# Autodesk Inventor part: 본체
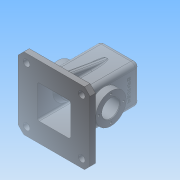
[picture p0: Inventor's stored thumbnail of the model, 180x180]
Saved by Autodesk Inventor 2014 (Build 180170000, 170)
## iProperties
Created: 2016-02
Part Number: 본체
Material: 일반
Document SubType Name: Modeling
Designer: net
Density: 1 g/cm^3
Appearance: 기본값
Author: net
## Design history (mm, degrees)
sketch "스케치1"
  geometry: L1 (55, -65)-(-55, -65); L2 (-65, -55)-(-65, 55); L3 (-55, 65)-(55, 65); L4 (65, 55)-(65, -55); L5 (55, -65)-(65, -55); L6 (65, 55)-(55, 65); L7 (-55, 65)-(-65, 55); L8 (-65, -55)-(-55, -65); 5 further points
  constraints: 16 end point, 8 point on line, 2 parallel, 1 horizontal, 1 perpendicular
  dimensions: "d0" = 130 distance of point (65, -65) point (-65, -65); "d1" = 130 distance of point (-65, -65) point (-65, 65); "d2" = 65 distance from line of point (0, 0) L4; "d3" = 65 distance from line of point (0, 0) L1; "d4" = 10 distance of L1.start point (65, -65); "d5" = 10 distance of L4.end point (65, -65) (= d4); "d6" = 10 distance of L4.start point (65, 65) (= d4); "d7" = 10 distance of L3.end point (65, 65) (= d6); "d8" = 10 distance of L3.start point (-65, 65) (= d4); "d9" = 10 distance of L2.end point (-65, 65) (= d8); "d10" = 10 distance of L2.start point (-65, -65) (= d4); "d11" = 10 distance of L1.end point (-65, -65) (= d10)
extrude "돌출1" new body sketch "스케치1" distance "d12" = 10; taper "d13" = 0 deg
sketch "스케치2"
  geometry: L1 (-35, 35)-(35, 35); L2 (35, 35)-(35, -35); L3 (35, -35)-(-35, -35); L4 (-35, -35)-(-35, 35); 1 further point
  constraints: 8 end point, 2 parallel, 1 horizontal, 1 perpendicular
  dimensions: "d14" = 70 distance of L1.start L1.end; "d15" = 70 distance of L1.end L2.end; "d16" = 35 distance from line of point (0, 0) L1; "d17" = 35 distance from line of point (0, 0) L2
extrude "돌출2" join sketch "스케치2" distance "d18" = 110; taper "d19" = 0 deg
sketch "스케치3"
  geometry: L1 (0, 65)-(10, 65) reference; L2 (10, 65)-(10, 50); L3 (10, 50)-(95.069, 35); L4 (10, 35)-(120, 35) reference; L5 (10, 50)-(10, 35); L6 (10, 35)-(95.069, 35); L7 (10, -50)-(95.069, -35); L8 (10, -50)-(10, -35); L9 (10, -35)-(95.069, -35); L10 (120, -35)-(120, 35) reference; L11 (10, -35)-(120, -35) reference; L12 (-12.76, 30)-(115, 30); L13 (115, 30)-(115, -30); L14 (115, -30)-(-12.76, -30); L15 (-12.76, 30)-(-12.76, -30); 1 further point
  constraints: 22 end point, 3 perpendicular
  dimensions: "d20" = 15 distance of L1.end L2.end; "d21" = 10 deg angle of L1 L3; "d22" = 5 distance between parallel lines of L12 L4; "d23" = 5 distance between parallel lines of L10 L13; "d24" = 5 distance between parallel lines of L11 L14
extrude "돌출3" cut sketch "스케치3" stored distance "d25" = 60; taper "d26" = 0 deg
extrude "돌출4" join sketch "스케치3" stored distance "d27" = 10; taper "d28" = 0 deg
sketch "스케치4"
  geometry: L1 (0, 0)-(0, 55); L2 (0, 55)-(-48, 55); L3 (0, 55)-(48, 55)
  constraints: 6 end point, 1 collinear, 1 perpendicular, 1 vertical
  dimensions: "d29" = 55 distance of L1.start L1.end; "d30" = 48 distance of L1.end L2.end; "d31" = 48 distance of L1.end L3.end
node "작업 평면1"
node "작업 평면2"
sketch "스케치7"
  geometry: L1 (-30, 0)-(-30, 115) reference; L2 (0, 0)-(0, 55); C1 r 27.5 at (0, 55)
  constraints: 2 end point, 1 centre point, 1 coincident, 1 parallel
  dimensions: "d38" = 55 distance of L2.start L2.end; "d39" = 27.5 radius of C1
extrude "돌출7" join sketch "스케치7" distance "d40" = 7; taper "d41" = 0 deg
sketch "스케치8"
  geometry: L1 (-30, 0)-(-30, 115) reference; L2 (0, 0)-(0, 55); C1 r 27.5 at (0, 55)
  constraints: 2 end point, 1 centre point, 1 coincident, 1 parallel
  dimensions: "d42" = 55 distance of L2.start L2.end; "d43" = 27.5 radius of C1
extrude "돌출8" join sketch "스케치8" distance "d44" = 7; taper "d45" = 0 deg
feature "면 기울기1" dims angle "d46" = 45 deg
feature "면 기울기2" dims angle "d47" = 45 deg
sketch "스케치11"
  geometry: C1 r 20 at (0, 0); 1 further point
  constraints: 1 centre point, 1 coincident
  dimensions: "d95" = 20 radius of C1
extrude "돌출9" join sketch "스케치11" distance "d96" = 10; taper "d97" = 0 deg
feature "면 기울기3" dims angle "d98" = 10 deg
hole "구멍4" diameter "d101" = 21; stored, may be unused: countersink angle "d105" = 90 deg, drill point angle "d107" = 118 deg; dims "d99" = 10, "d100" = 10, "d102" = 6, "d103" = 28, "d104" = 4, "d106" = 10
hole "구멍5" diameter "d110" = 12; stored, may be unused: countersink angle "d114" = 90 deg, drill point angle "d116" = 118 deg; dims "d108" = 15, "d109" = 15, "d111" = 6, "d112" = 28, "d113" = 4, "d115" = 10
hole "구멍6" diameter "d119" = 12; stored, may be unused: countersink angle "d123" = 90 deg, drill point angle "d125" = 118 deg; dims "d117" = 15, "d118" = 15, "d120" = 6, "d121" = 28, "d122" = 4, "d124" = 10
hole "구멍7" diameter "d128" = 12; stored, may be unused: countersink angle "d132" = 90 deg, drill point angle "d134" = 118 deg; dims "d126" = 15, "d127" = 15, "d129" = 6, "d130" = 28, "d131" = 4, "d133" = 10
hole "구멍8" diameter "d137" = 12; stored, may be unused: countersink angle "d141" = 90 deg, drill point angle "d143" = 118 deg; dims "d135" = 15, "d136" = 15, "d138" = 6, "d139" = 28, "d140" = 4, "d142" = 10
fillet "모깎기2" dims "d145" = 3
fillet "모깎기3" dims "d146" = 3
fillet "모깎기4" dims "d147" = 0.5
fillet "모깎기7" dims "d153" = 8
fillet "모깎기8" dims "d154" = 8
sketch "스케치13"
  geometry: L1 (54, 102)-(54, 0) reference; L2 (27, -10)-(27, 45); C1 r 27.5 at (27, 45)
  constraints: 2 end point, 1 centre point, 1 coincident, 1 parallel
  dimensions: "d155" = 55 distance of L2.start L2.end; "d156" = 27.5 radius of C1
extrude "돌출10" join sketch "스케치13" distance "d157" = 13; taper "d158" = 0 deg
fillet "모깎기9" dims "d159" = 0.5
sketch "스케치14"
  geometry: L1 (54, 102)-(54, 0) reference; L2 (27, -10)-(27, 45); C1 r 27.5 at (27, 45)
  constraints: 2 end point, 1 centre point, 1 coincident, 1 parallel
  dimensions: "d160" = 55 distance of L2.start L2.end; "d161" = 27.5 radius of C1
extrude "돌출11" join sketch "스케치14" distance "d162" = 13; taper "d163" = 0 deg
fillet "모깎기10" dims "d164" = 0.5
hole "구멍9" diameter "d167" = 32; stored, may be unused: countersink angle "d171" = 90 deg, drill point angle "d173" = 118 deg; dims "d165" = 10, "d166" = 10, "d168" = 6, "d169" = 28, "d170" = 4, "d172" = 10
sketch "스케치15"
  geometry: L1 (0, 0)-(0, 22.5); C1 r 27.5 at (0, 0) reference; 1 further point
  constraints: 2 end point, 1 vertical
  dimensions: "d174" = 22.5 distance of L1.start L1.end
hole "구멍10" sketch "스케치15" at (0, 22.5) diameter "d175" = 4; stored, may be unused: countersink angle "d179" = 90 deg, drill point angle "d181" = 118 deg; dims "d176" = 6, "d177" = 28, "d178" = 4, "d180" = 10
sketch "스케치16"
  geometry: L1 (0, 0)-(0, 22.5); C1 r 27.5 at (0, 0) reference; 1 further point
  constraints: 2 end point, 1 vertical
  dimensions: "d182" = 22.5 distance of L1.start L1.end
hole "구멍11" sketch "스케치16" at (0, 22.5) diameter "d183" = 4; stored, may be unused: countersink angle "d187" = 90 deg, drill point angle "d189" = 118 deg; dims "d184" = 6, "d185" = 28, "d186" = 4, "d188" = 10
feature "스레드9" dims "d196" = 8, "d197" = 0
feature "스레드10" dims "d198" = 8, "d199" = 0
feature "스레드11" dims "d200" = 8, "d201" = 0
feature "스레드12" dims "d202" = 8, "d203" = 0
feature "스레드13" dims "d204" = 8, "d205" = 0
feature "스레드14" dims "d206" = 8, "d207" = 0
feature "스레드15" dims "d208" = 8, "d209" = 0
feature "스레드16" dims "d210" = 8, "d211" = 0
sketch "스케치17"
  geometry: L1 (45.237, 18)-(8.763, 18) reference; L2 (27, 18)-(27, -12); L3 (6.533, -8.675)-(48.012, -8.675); L4 (48.012, -8.675)-(48.012, -14.679); L5 (48.012, -14.679)-(6.533, -14.679); L6 (6.533, -14.679)-(6.533, -8.675); 1 further point
  constraints: 2 end point, 1 midpoint, 1 perpendicular, 2 other
  dimensions: "d212" = 30 distance of L2.start L2.end
feature "엠보싱2" sketch "스케치17" dims "d213" = 0.5, "d214" = 0
fillet "모깎기11" dims "d215" = 3
fillet "모깎기12" dims "d216" = 3
fillet "모깎기13" dims "d217" = 3
chamfer "모따기1" distance "d218" = 1; stored, may be unused: second distance "d219" = 2, angle "d220" = 45 deg
node "솔리드1"
pattern_circular "원형 패턴3" dims angle "d191" = 360 deg
pattern_circular "원형 패턴4" dims angle "d194" = 360 deg
